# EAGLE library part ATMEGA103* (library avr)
MICROCONTROLLER Low-voltage (L) 128 Kbytes FLASH 4 Kbytes SRAM 2 Kbytes EEPROM UART RTC 8-channel 10 bit ADC
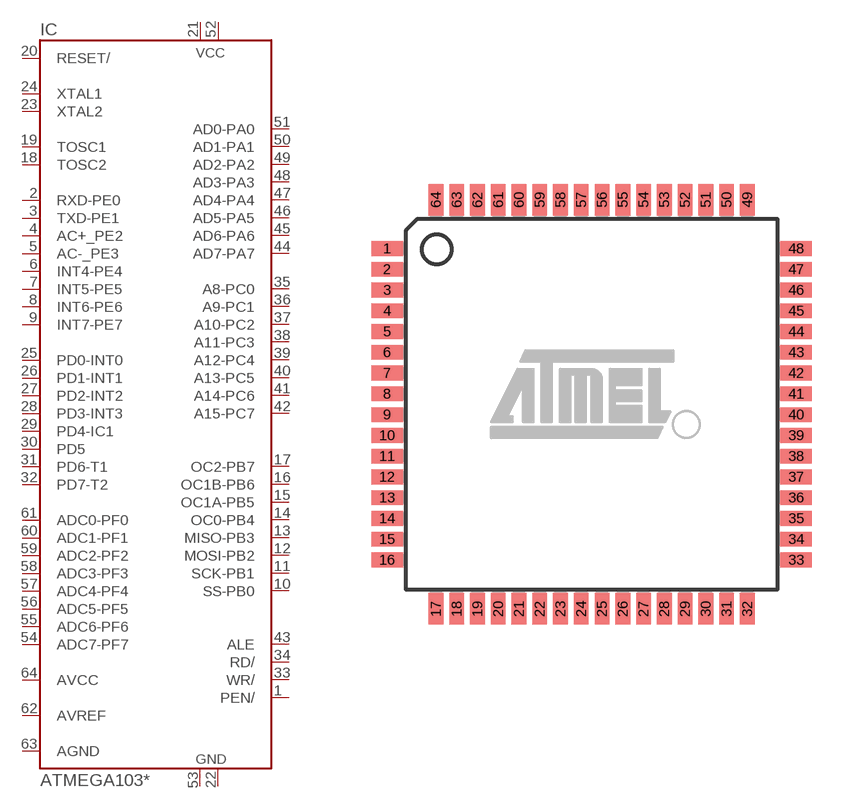
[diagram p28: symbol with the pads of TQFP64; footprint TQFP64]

Designator prefix IC

## ATMEGA103-8A, ATMEGA103L-4A  [TQFP64]
1  PEN/  in
2  RXD-PE0  out
3  TXD-PE1  out
4  AC+_PE2  out
5  AC-_PE3  out
6  INT4-PE4  out
7  INT5-PE5  out
8  INT6-PE6  out
9  INT7-PE7  out
10  SS-PB0
11  SCK-PB1
12  MOSI-PB2
13  MISO-PB3
14  OC0-PB4
15  OC1A-PB5
16  OC1B-PB6
17  OC2-PB7
18  TOSC2
19  TOSC1
20  RESET/  in
21  01  pwr
22  02  pwr
23  XTAL2
24  XTAL1
25  PD0-INT0
26  PD1-INT1
27  PD2-INT2
28  PD3-INT3
29  PD4-IC1
30  PD5
31  PD6-T1
32  PD7-T2
33  WR/
34  RD/
35  A8-PC0
36  A9-PC1
37  A10-PC2
38  A11-PC3
39  A12-PC4
40  A13-PC5
41  A14-PC6
42  A15-PC7
43  ALE
44  AD7-PA7
45  AD6-PA6
46  AD5-PA5
47  AD4-PA4
48  AD3-PA3
49  AD2-PA2
50  AD1-PA1
51  AD0-PA0
52  VCC  pwr
53  GND  pwr
54  ADC7-PF7  in
55  ADC6-PF6  in
56  ADC5-PF5  in
57  ADC4-PF4  in
58  ADC3-PF3  in
59  ADC2-PF2  in
60  ADC1-PF1  in
61  ADC0-PF0  in
62  AVREF
63  AGND
64  AVCC

## Footprint TQFP64 (pad centres in mm)
Thin Plasic Quad Flat Package
smd 1.194 x 0.559: 1 -7.76,5.905; 2 -7.76,5.118; 3 -7.76,4.331; 4 -7.76,3.543; 5 -7.76,2.756; 6 -7.76,1.968; 7 -7.76,1.181; 8 -7.76,0.394; 9 -7.76,-0.394; 10 -7.76,-1.181; 11 -7.76,-1.968; 12 -7.76,-2.756; 13 -7.76,-3.543; 14 -7.76,-4.331; 15 -7.76,-5.118; 16 -7.76,-5.905; 33 7.76,-5.905; 34 7.76,-5.118; 35 7.76,-4.331; 36 7.76,-3.543; 37 7.76,-2.756; 38 7.76,-1.968; 39 7.76,-1.181; 40 7.76,-0.394; 41 7.76,0.394; 42 7.76,1.181; 43 7.76,1.968; 44 7.76,2.756; 45 7.76,3.543; 46 7.76,4.331; 47 7.76,5.118; 48 7.76,5.905
smd 0.559 x 1.194: 17 -5.905,-7.76; 18 -5.118,-7.76; 19 -4.331,-7.76; 20 -3.543,-7.76; 21 -2.756,-7.76; 22 -1.968,-7.76; 23 -1.181,-7.76; 24 -0.394,-7.76; 25 0.394,-7.76; 26 1.181,-7.76; 27 1.968,-7.76; 28 2.756,-7.76; 29 3.543,-7.76; 30 4.331,-7.76; 31 5.118,-7.76; 32 5.905,-7.76; 49 5.905,7.76; 50 5.118,7.76; 51 4.331,7.76; 52 3.543,7.76; 53 2.756,7.76; 54 1.968,7.76; 55 1.181,7.76; 56 0.394,7.76; 57 -0.394,7.76; 58 -1.181,7.76; 59 -1.968,7.76; 60 -2.756,7.76; 61 -3.543,7.76; 62 -4.331,7.76; 63 -5.118,7.76; 64 -5.905,7.76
